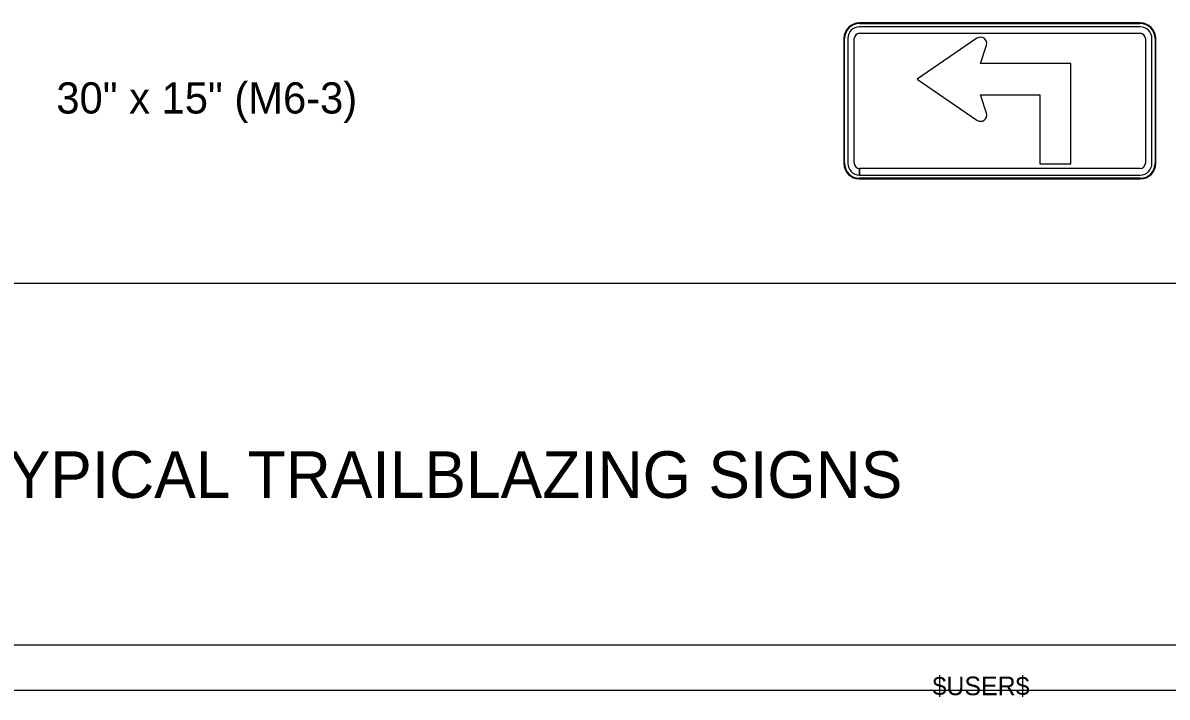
# Model space of a CAD drawing. Extents: x 17890587 to 17890754, y 17897693 to 17897992.
# Drawn here: x 17890622.18 to 17890629.6, y 17897873.06 to 17897877.43 of the extents above; entities that cross this region are included whole.
import ezdxf

# ---------------------------------------------------------------- set-up
doc = ezdxf.new("R2010")
doc.units = 0
for name, color, linetype in [('GSBWFill', 7, 'Continuous'), ('GSColorFill', 7, 'Continuous'), ('GSOutline', 7, 'Continuous'), ('PlotBorder_dp', 7, 'Continuous'), ('SheetBorder_dp', 7, 'Continuous'), ('TextMisc', 7, 'Continuous')]:
    doc.layers.add(name, color=color, linetype=linetype)

msp = doc.modelspace()

# ---------------------------------------------------------------- linework, layer by layer
at = {"layer": 'GSBWFill'}
msp.add_line((17890628.4322, 17897876.8471), (17890628.3943, 17897876.9665), dxfattribs=at)
for points in [[(17890628.3707, 17897877.334), (17890627.9826, 17897877.0677), (17890628.3707, 17897876.8016)], [(17890628.3943, 17897876.9665), (17890628.7781, 17897876.9665), (17890628.7781, 17897876.5183), (17890628.9805, 17897876.5183), (17890628.9805, 17897877.169), (17890628.3943, 17897877.169), (17890628.4322, 17897877.2883)]]:
    msp.add_lwpolyline(points, dxfattribs=at)
for centre, major_axis, start_param, end_param in [((17890628.3936, 17897877.3006), (0.0405, 0), 5.975991, 8.455234), ((17890628.3936, 17897876.8349), (-0.0405, 0), 0.969544, 3.448787)]:
    msp.add_ellipse(centre, major_axis=major_axis, ratio=0.999895, start_param=start_param, end_param=end_param, dxfattribs=at)
at = {"layer": 'GSColorFill'}
for p, q in [((17890629.4302, 17897877.4331), (17890627.6079, 17897877.4331)), ((17890629.4302, 17897877.4331), (17890627.6079, 17897877.4331)), ((17890627.6079, 17897877.4289), (17890629.4302, 17897877.4289)), ((17890629.4302, 17897877.4078), (17890627.6079, 17897877.4078)), ((17890627.5066, 17897877.3318), (17890627.5066, 17897876.5219)), ((17890627.5066, 17897877.3318), (17890627.5066, 17897876.5219)), ((17890627.5109, 17897876.5219), (17890627.5109, 17897877.3318)), ((17890627.532, 17897877.3318), (17890627.532, 17897876.5219)), ((17890627.5741, 17897876.5219), (17890627.5741, 17897877.3318)), ((17890627.6079, 17897877.3656), (17890629.4302, 17897877.3656)), ((17890629.464, 17897877.3318), (17890629.464, 17897876.5219)), ((17890629.5061, 17897876.5219), (17890629.5061, 17897877.3318)), ((17890629.5272, 17897877.3318), (17890629.5272, 17897876.5219)), ((17890629.5314, 17897876.5219), (17890629.5314, 17897877.3318)), ((17890629.5314, 17897876.5219), (17890629.5314, 17897877.3318)), ((17890628.4322, 17897876.8471), (17890628.3943, 17897876.9665)), ((17890627.6079, 17897876.446), (17890627.6079, 17897876.4882)), ((17890627.6079, 17897876.4207), (17890627.6079, 17897876.4249)), ((17890629.4302, 17897876.4249), (17890627.6079, 17897876.4249)), ((17890627.6079, 17897876.4249), (17890627.6079, 17897876.4207)), ((17890627.6079, 17897876.4207), (17890629.4302, 17897876.4207)), ((17890627.6079, 17897876.4207), (17890629.4302, 17897876.4207)), ((17890629.4302, 17897876.4882), (17890627.6083, 17897876.4882)), ((17890627.6083, 17897876.4882), (17890627.6083, 17897876.446)), ((17890627.6083, 17897876.446), (17890629.4302, 17897876.446))]:
    msp.add_line(p, q, dxfattribs=at)
for points in [[(17890628.3707, 17897877.334), (17890627.9826, 17897877.0677), (17890628.3707, 17897876.8016)], [(17890628.3943, 17897876.9665), (17890628.7781, 17897876.9665), (17890628.7781, 17897876.5183), (17890628.9805, 17897876.5183), (17890628.9805, 17897877.169), (17890628.3943, 17897877.169), (17890628.4322, 17897877.2883)]]:
    msp.add_lwpolyline(points, dxfattribs=at)
for centre, radius, start, end in [((17890627.6079, 17897877.3318), 0.1012, 90, 180), ((17890627.6079, 17897877.3318), 0.1012, 90, 180), ((17890627.6079, 17897877.3318), 0.097, 90, 180), ((17890627.6079, 17897877.3318), 0.0759, 90, 180), ((17890629.4302, 17897877.3318), 0.1012, 0, 90), ((17890629.4302, 17897877.3318), 0.1012, 0, 90), ((17890629.4302, 17897877.3318), 0.097, 0, 90), ((17890629.4302, 17897877.3318), 0.0759, 0, 90), ((17890627.6079, 17897877.3318), 0.0337, 90, 180), ((17890629.4302, 17897877.3318), 0.0337, 0, 90), ((17890627.6079, 17897876.5219), 0.1012, 180, 270), ((17890627.6079, 17897876.5219), 0.1012, 180, 270), ((17890627.6079, 17897876.5219), 0.097, 180, 270), ((17890627.6079, 17897876.5219), 0.0759, 180, 270), ((17890627.6079, 17897876.5219), 0.0337, 180, 270), ((17890629.4302, 17897876.5219), 0.1012, 270, 0), ((17890629.4302, 17897876.5219), 0.1012, 270, 0), ((17890629.4302, 17897876.5219), 0.097, 270, 0), ((17890629.4302, 17897876.5219), 0.0759, 270, 0), ((17890629.4302, 17897876.5219), 0.0337, 270, 0)]:
    msp.add_arc(centre, radius, start, end, dxfattribs=at)
for centre, major_axis, start_param, end_param in [((17890628.3936, 17897877.3006), (0.0405, 0), 5.975991, 8.455234), ((17890628.3936, 17897876.8349), (-0.0405, 0), 0.969544, 3.448787)]:
    msp.add_ellipse(centre, major_axis=major_axis, ratio=0.999895, start_param=start_param, end_param=end_param, dxfattribs=at)
at = {"layer": 'GSOutline'}
msp.add_line((17890628.4322, 17897876.8471), (17890628.3943, 17897876.9665), dxfattribs=at)
for points in [[(17890628.3707, 17897877.334), (17890627.9826, 17897877.0677), (17890628.3707, 17897876.8016)], [(17890628.3943, 17897876.9665), (17890628.7781, 17897876.9665), (17890628.7781, 17897876.5183), (17890628.9805, 17897876.5183), (17890628.9805, 17897877.169), (17890628.3943, 17897877.169), (17890628.4322, 17897877.2883)]]:
    msp.add_lwpolyline(points, dxfattribs=at)
for centre, major_axis, start_param, end_param in [((17890628.3936, 17897877.3006), (0.0405, 0), 5.975991, 8.455234), ((17890628.3936, 17897876.8349), (-0.0405, 0), 0.969544, 3.448787)]:
    msp.add_ellipse(centre, major_axis=major_axis, ratio=0.999895, start_param=start_param, end_param=end_param, dxfattribs=at)
at = {"layer": 'PlotBorder_dp'}
msp.add_lwpolyline([(17890586.7562, 17897873.1039), (17890635.165, 17897873.1039), (17890635.165, 17897904.2029), (17890586.7562, 17897904.2029)], close=True, dxfattribs=at)
at = {"layer": 'SheetBorder_dp'}
for p, q in [((17890588.3699, 17897875.7444), (17890633.5514, 17897875.7444)), ((17890588.3699, 17897873.3973), (17890633.5514, 17897873.3973))]:
    msp.add_line(p, q, dxfattribs=at)

# ---------------------------------------------------------------- texts
at = {"layer": 'TextMisc'}
for s, height, p in [('30" x 15" (M6-3)', 0.202479, (17890622.3949, 17897876.8451)), ('TYPICAL TRAILBLAZING SIGNS', 0.302553, (17890621.8386, 17897874.3505)), ('$USER$', 0.12102, (17890628.0822, 17897873.0701))]:
    msp.add_text(s, height=height, dxfattribs=at).set_placement(p)

doc.saveas('drawing.dxf')
